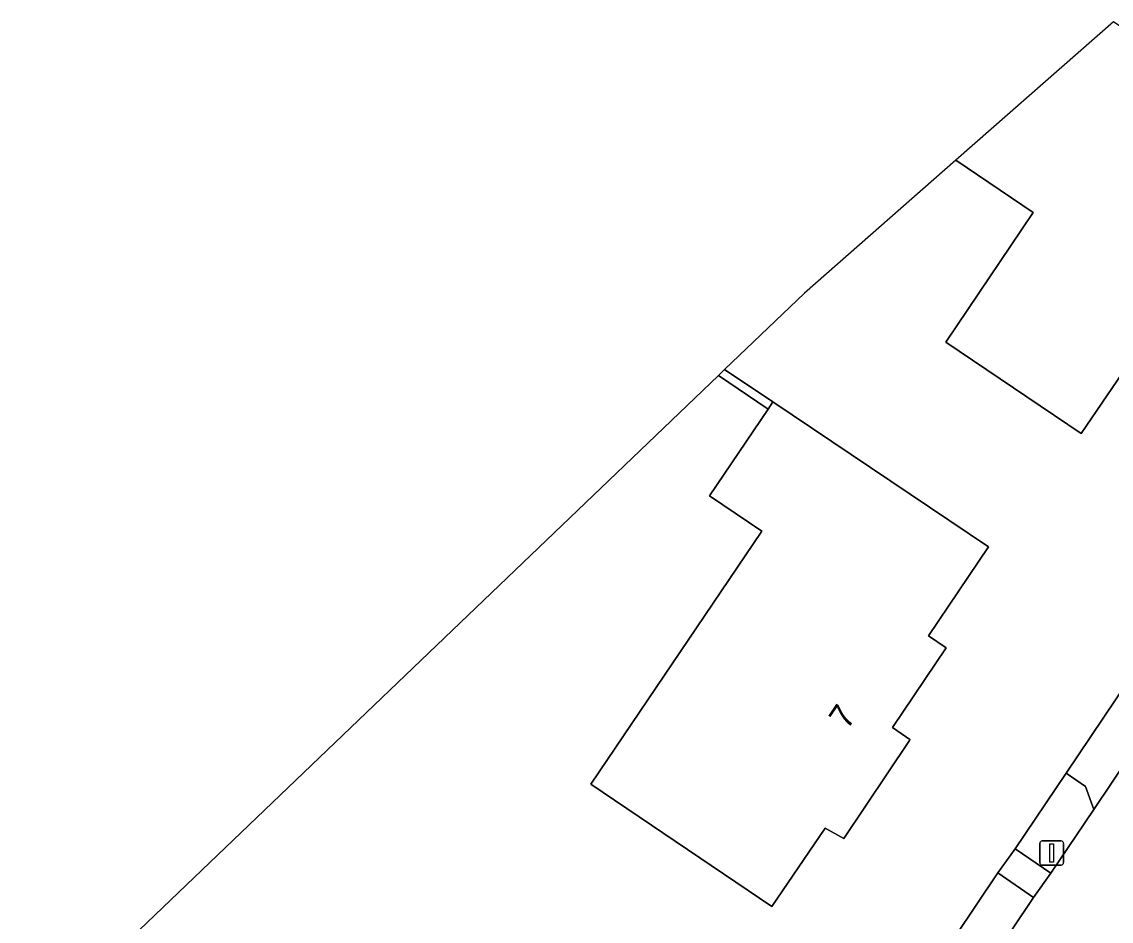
# Model space of a CAD drawing. Extents: x 163859 to 164644, y 379566 to 382155.
# Drawn here: x 164129.44 to 164174.78, y 381819.51 to 381856.93 of the extents above; entities that cross this region are included whole.
import ezdxf

# ---------------------------------------------------------------- set-up
doc = ezdxf.new("R2010")
doc.units = 0
for name, color, linetype in [('IMGEO_Erf', 7, 'Continuous'), ('IMGEO_Lichtmast', 7, 'Continuous'), ('IMGEO_Muur', 7, 'Continuous'), ('IMGEO_Pand', 7, 'Continuous'), ('IMGEO_Pand_nummerreeks', 7, 'Continuous'), ('IMGEO_Rijbaan_lokaal_open', 7, 'Continuous'), ('IMGEO_Voetpad_halfverhard', 7, 'Continuous'), ('IMGEO_Voetpad_open', 7, 'Continuous')]:
    doc.layers.add(name, color=color, linetype=linetype)

msp = doc.modelspace()

# ---------------------------------------------------------------- linework, layer by layer
at = {"layer": 'IMGEO_Erf'}
for points in [[(164177.173, 381845.157), (164173.526, 381839.8), (164167.892, 381843.609), (164171.538, 381849.002), (164168.319, 381851.178), (164162.013, 381845.645), (164158.69, 381842.464), (164160.699, 381841.115), (164169.668, 381835.093), (164167.176, 381831.382), (164167.907, 381830.882), (164165.684, 381827.566), (164166.4, 381827.07), (164166.393, 381827.026), (164163.648, 381822.952), (164162.877, 381823.383), (164160.657, 381820.12), (164153.12, 381825.219), (164160.236, 381835.738), (164158.058, 381837.212), (164160.501, 381840.823), (164158.435, 381842.22), (164129.443, 381814.469)], [(164159.489, 381805.76), (164170.069, 381821.522), (164170.786, 381822.53), (164172.905, 381825.67), (164176.013, 381830.292)]]:
    msp.add_lwpolyline(points, dxfattribs=at)
at = {"layer": 'IMGEO_Lichtmast'}
for p, q in [((164171.808, 381821.951), (164171.808, 381822.751)), ((164171.808, 381822.751), (164171.808, 381821.951)), ((164171.908, 381822.851), (164172.698, 381822.851)), ((164172.698, 381822.851), (164171.908, 381822.851)), ((164172.798, 381822.751), (164172.798, 381821.951)), ((164172.798, 381821.951), (164172.798, 381822.751)), ((164172.698, 381821.851), (164171.908, 381821.851)), ((164171.908, 381821.851), (164172.698, 381821.851))]:
    msp.add_line(p, q, dxfattribs=at)
msp.add_lwpolyline([(164172.228, 381822.726), (164172.378, 381822.726), (164172.378, 381821.976), (164172.228, 381821.976), (164172.228, 381822.726)], dxfattribs=at)
for centre, start, end in [((164171.908, 381822.751), 90, 180), ((164171.908, 381822.751), 90, 180), ((164172.698, 381822.751), 0, 90), ((164172.698, 381822.751), 360, 90), ((164171.908, 381821.951), 180, 270), ((164171.908, 381821.951), 180, 270), ((164172.698, 381821.951), 270, 0), ((164172.698, 381821.951), 270, 0)]:
    msp.add_arc(centre, 0.1, start, end, dxfattribs=at)
at = {"layer": 'IMGEO_Muur'}
msp.add_lwpolyline([(164158.435, 381842.22), (164160.501, 381840.823), (164160.699, 381841.115), (164158.69, 381842.464)], close=True, dxfattribs=at)
at = {"layer": 'IMGEO_Pand'}
for points in [[(164174.878, 381856.933), (164168.319, 381851.178), (164171.538, 381849.002), (164167.892, 381843.609), (164173.526, 381839.8), (164177.173, 381845.157), (164178.088, 381844.548), (164182.827, 381851.535)], [(164169.668, 381835.093), (164160.699, 381841.115), (164160.501, 381840.823), (164158.058, 381837.212), (164160.236, 381835.738), (164153.12, 381825.219), (164160.657, 381820.12), (164162.877, 381823.383), (164163.648, 381822.952), (164166.393, 381827.026), (164166.4, 381827.07), (164165.684, 381827.566), (164167.907, 381830.882), (164167.176, 381831.382)]]:
    msp.add_lwpolyline(points, close=True, dxfattribs=at)
at = {"layer": 'IMGEO_Rijbaan_lokaal_open'}
msp.add_lwpolyline([(164194.609, 381854.612), (164194.104, 381853.864), (164192.817, 381851.959), (164186.204, 381842.193), (164185.505, 381841.141), (164183.67, 381838.426), (164181.218, 381834.798), (164177.875, 381829.852), (164174.051, 381824.163), (164172.275, 381821.514), (164171.541, 381820.495), (164165.146, 381810.963), (164168.994, 381808.366), (164183.294, 381829.671)], dxfattribs=at)
msp.add_lwpolyline([(164177.875, 381829.852), (164176.867, 381829.747), (164176.013, 381830.292), (164172.905, 381825.67), (164173.716, 381825.119), (164174.051, 381824.163)], close=True, dxfattribs=at)
at = {"layer": 'IMGEO_Voetpad_halfverhard'}
for points in [[(164174.051, 381824.163), (164173.716, 381825.119), (164172.905, 381825.67), (164170.786, 381822.53), (164172.275, 381821.514)], [(164171.541, 381820.495), (164170.069, 381821.522), (164159.489, 381805.76), (164160.947, 381804.756), (164163.204, 381808.122), (164165.146, 381810.963)]]:
    msp.add_lwpolyline(points, close=True, dxfattribs=at)
at = {"layer": 'IMGEO_Voetpad_open'}
msp.add_lwpolyline([(164172.275, 381821.514), (164170.786, 381822.53), (164170.069, 381821.522), (164171.541, 381820.495)], close=True, dxfattribs=at)

# ---------------------------------------------------------------- texts
at = {"layer": 'IMGEO_Pand_nummerreeks'}
msp.add_text('7', height=1, rotation=56.1613, dxfattribs=at).set_placement((164163.8, 381827.449))

doc.saveas('drawing.dxf')
